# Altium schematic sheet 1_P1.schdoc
size 309 x 223 mm; Symbol: Sheet-Symbol_A4; Device: Sheet-Symbol_A4; @Page Name: P1; @Create Date: 2024-03-22; @Page Count: 1; @Page No: 1; @Project Name: ECE590; @Schematic Name: Schematic2; @Update Date: 2024-03-21; Company: 嘉立创EDA; Page Size: A4; Version: V1.0
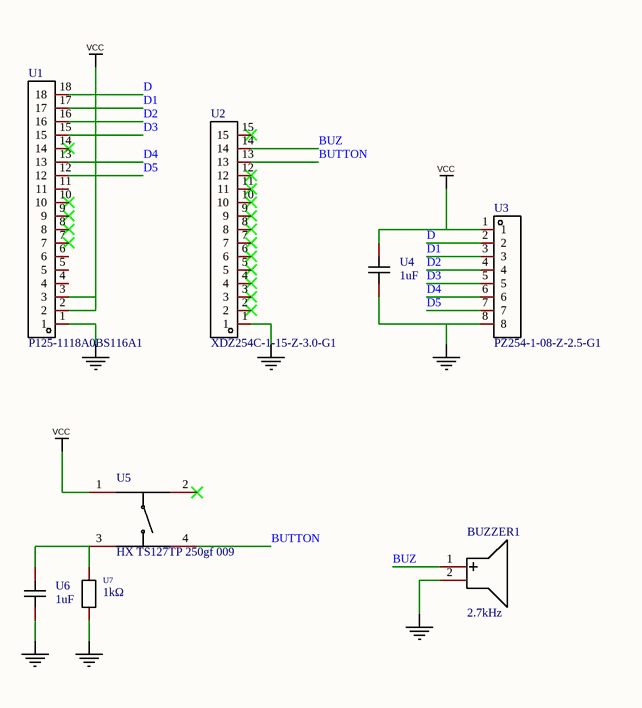
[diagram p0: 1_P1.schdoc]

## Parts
BUZZER1  2.7kHz  [BUZ-TH_BD9.0-P5.00-D0.6-FD]
U1  P125-1118A0BS116A1  [HDR-TH_18P-P2.54-V-M]
U2  XDZ254C-1-15-Z-3.0-G1  [HDR-TH_15P-P2.54-V-M]
U3  PZ254-1-08-Z-2.5-G1  [HDR-TH_8P-P2.54-V-M]
U4  1uF  [C0603]
U5  HX TS127TP 250gf 009  [SW-SMD_4P-L12.0-W12.0-P5.00-LS15.4]
U6  1uF  [C0603]
U7  1kΩ  [R0603]

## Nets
NetBUZZER1_2: BUZZER1.2(-) U1.1 U2.1 U3.8 U4.1 U6.1 U7.1
VCC: U1.2 U1.3 U3.1 U4.2 U5.1(A)
BUTTON: U2.13 U5.4(D)
BUZ: BUZZER1.1(+) U2.14
D: U1.18 U3.2
D1: U1.17 U3.3
D2: U1.16 U3.4
D3: U1.15 U3.5
D4: U1.13 U3.6
D5: U1.12 U3.7
NetU5_3: U5.3(C) U6.2 U7.2

Not connected (* = marked no-connect by the designer): U1 4 5 6 7* 8* 9* 10* 11 14*; U2 2* 3* 4* 5* 6* 7* 8* 9* 10* 11* 12* 15*; U5 2(B)*

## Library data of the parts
BUZZER1 = YS-MBZ9055DYB03: 驱动方式:有源(内含驱动线路);构造类型:电磁式;频率:2.7kHz;声压(SPL):85dB@3V,10cm;; Manufacturer: Fengming(锋鸣电子); Symbol: YS-MBZ9055DYB03_C409835; Add into BOM: yes; Technology Type: 电磁式; Operating Voltage: 2V~5V
U1 = P125-1118A0BS116A1: 插针结构:1x18P;间距:2.54mm;行距:2.54mm;圆针/方针:方针;安装类型:直插;排数:单排;总PIN位数:18P;配合针长度:6mm;塑高:2.5mm;端接针长度:3mm;触头材质:黄铜;触头镀层:金;工作温度范围:-40℃~+105℃;颜色:黑色;; Manufacturer: Yxcon(宇熙精密); Add into BOM: yes; Pin Structure: 1x18P; Pitch: 2.54mm; Circluar Pins/Square Pins: 方针
U2 = XDZ254C-1-15-Z-3.0-G1: 插针结构:1x15P;间距:2.54mm;行距:2.54mm;圆针/方针:圆针;安装类型:直插;排数:单排;总PIN位数:15P;额定电流:3A;配合针长度:4.1mm;塑高:3mm;端接针长度:4.1mm;触头材质:黄铜;触头镀层:金;工作温度范围:-40℃~+105℃;焊接温度(最大值):260℃;颜色:黑色;; Manufacturer: XUNDA(讯答); Add into BOM: yes; Pin Structure: 1x15P; Pitch: 2.54mm; Circluar Pins/Square Pins: 圆针; Current Rating (Max): 3A; Soldering Temperature(Max): 260℃
U3 = PZ254-1-08-Z-2.5-G1: 插针结构:1x8P;间距:2.54mm;行距:-;圆针/方针:方针;安装类型:直插;排数:单排;总PIN位数:8P;额定电流:3A;配合针长度:6mm;塑高:2.5mm;端接针长度:3mm;触头材质:黄铜;工作温度范围:-40℃~+105℃;焊接温度(最大值):260℃@10S;颜色:黑色;; Manufacturer: HCTL(华灿天禄); Add into BOM: yes; Pin Structure: 1x8P; Pitch: 2.54mm; Circluar Pins/Square Pins: 方针; Current Rating (Max): 3A
U4 U6 = VJ0603Y105KXJCW1BC: 容值:1uF;精度:±10%;额定电压:16V;材质(温度系数):X7R;; Manufacturer: VISHAY(威世); Add into BOM: yes; Tolerance: ±10%; Voltage Rated: 16V; Temperature Coefficient: X7R
U5 = HX TS127TP 250gf 009: 电路结构:单刀单掷;作用力:250gf;安装方式:立贴;开关长度:12mm;开关宽度:12mm;开关高度:7mm;带支架:不带;触点电流:50mA;额定电压(DC):12V;机械寿命:10万次;; Manufacturer: hanxia(韩下); Add into BOM: yes; Circuit: 单刀单掷; Switch Length: 12mm; Switch Height: 7mm; Strike Gundam: 不带; Contact Current: 50mA; Voltage Rating (DC): 12V; Mechanical Life: 10万次
U7 = AC0603JR-131KL: 电阻类型:厚膜电阻;阻值:1kΩ;精度:±5%;功率:100mW;最大工作电压:75V;温度系数:±100ppm/℃;; Manufacturer: YAGEO(国巨); Add into BOM: yes; Tolerance: ±5%; Power(Watts): 100mW; Overload Voltage (Max): 75V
